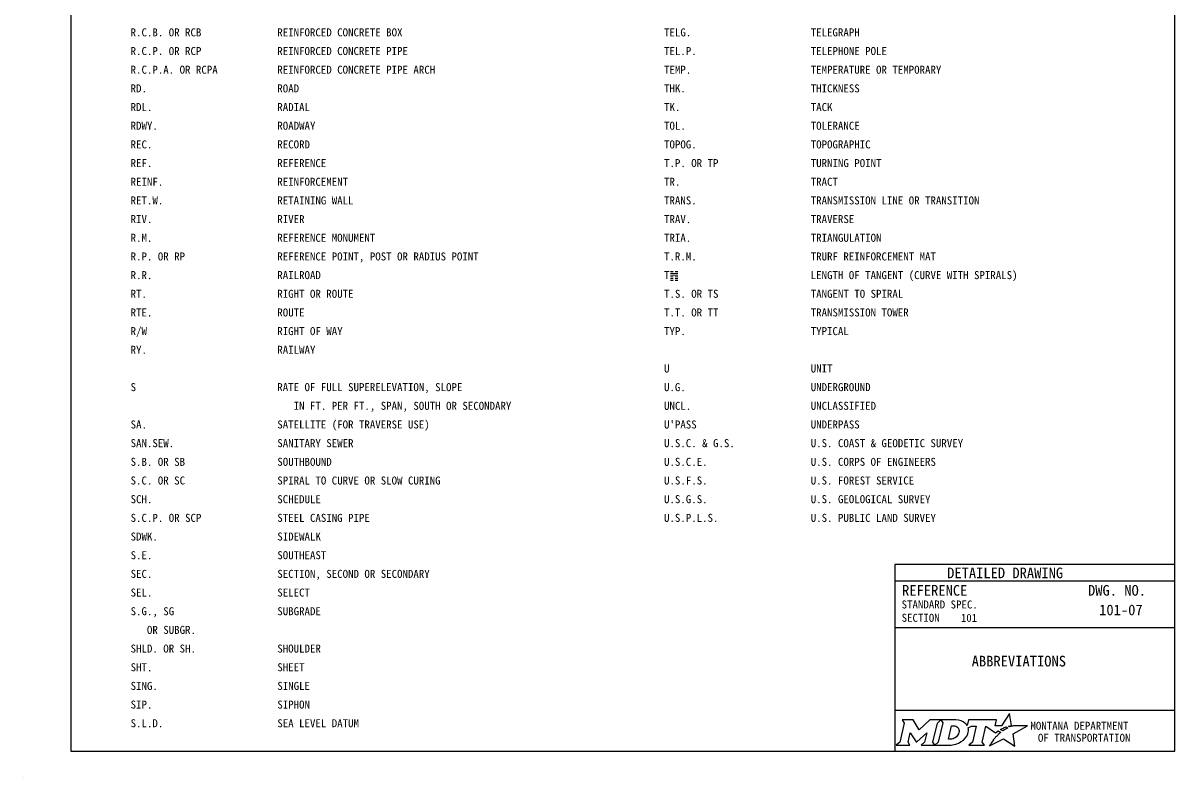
# Model space of a CAD drawing. Extents: x 49991.4 to 50021, y 49987.6 to 50011.4.
# Drawn here: x 49999.98 to 50008.61, y 49999.86 to 50005.52 of the extents above; entities that cross this region are included whole.
import ezdxf

# ---------------------------------------------------------------- set-up
doc = ezdxf.new("R2010")
doc.units = 0
for name, color, linetype in [('Level 1', 7, 'Continuous'), ('Level 2', 7, 'Continuous'), ('Level 5', 7, 'Continuous')]:
    doc.layers.add(name, color=color, linetype=linetype)

msp = doc.modelspace()

# ---------------------------------------------------------------- linework, layer by layer
at = {"layer": 'Level 1'}
msp.add_line((49999.9766, 49999.8624), (49999.9766, 49999.8624), dxfattribs=at)
msp.add_lwpolyline([(50008.6146, 50011.2628), (50000.3356, 50011.2628), (50000.3356, 50000.0624), (50008.6146, 50000.0624)], close=True, dxfattribs=at)
at = {"layer": 'Level 2'}
for p, q in [((50008.6146, 50001.4624), (50006.5146, 50001.4624)), ((50006.5146, 50001.4624), (50006.5146, 50000.0624)), ((50008.6146, 50001.3374), (50006.5146, 50001.3374)), ((50008.2507, 50001.1223), (50008.2507, 50001.1223)), ((50008.6146, 50000.9874), (50006.5146, 50000.9874)), ((50007.0089, 50001.0629), (50007.0089, 50001.0629)), ((50007.5646, 50000.7383), (50007.5646, 50000.7383)), ((50008.6146, 50000.3693), (50006.5146, 50000.3693))]:
    msp.add_line(p, q, dxfattribs=at)
for points in [[(50006.5701, 50000.2974), (50006.5842, 50000.274), (50006.5507, 50000.1307), (50006.525, 50000.1082), (50006.6266, 50000.1082), (50006.6131, 50000.131), (50006.6293, 50000.2011), (50006.673, 50000.1321), (50006.6783, 50000.1321), (50006.7534, 50000.2016), (50006.737, 50000.1305), (50006.7123, 50000.1085), (50006.8139, 50000.1085), (50006.8001, 50000.1318), (50006.8333, 50000.2742)], [(50006.8333, 50000.2742), (50006.8586, 50000.2974), (50006.7762, 50000.2974), (50006.6966, 50000.2244), (50006.6521, 50000.2971), (50006.5701, 50000.2974)], [(50006.9722, 50000.2974), (50006.8586, 50000.2974), (50006.8733, 50000.2745), (50006.8394, 50000.1307), (50006.8139, 50000.1085), (50006.9245, 50000.1085)], [(50007.3771, 50000.2447), (50007.3668, 50000.2503), (50007.3784, 50000.2531), (50007.39, 50000.2551), (50007.3726, 50000.3452), (50007.3131, 50000.2539), (50007.2658, 50000.2532), (50007.2761, 50000.2973), (50007.0669, 50000.2974), (50007.0568, 50000.2549), (50007.051, 50000.2632)], [(50006.9962, 50000.2107), (50006.995, 50000.2026), (50006.9918, 50000.1933), (50006.9876, 50000.1851), (50006.982, 50000.1776), (50006.9755, 50000.1707), (50006.9676, 50000.1644), (50006.9593, 50000.1597), (50006.9502, 50000.1558), (50006.9411, 50000.1535), (50006.9319, 50000.1526), (50006.916, 50000.1526), (50006.9396, 50000.2526), (50006.9556, 50000.2526), (50006.9632, 50000.252), (50006.9708, 50000.2501), (50006.9774, 50000.2471), (50006.9835, 50000.2429), (50006.9883, 50000.2379), (50006.992, 50000.2319), (50006.9947, 50000.2257), (50006.9963, 50000.2183), (50006.9963, 50000.2153), (50006.9962, 50000.2107)], [(50007.0636, 50000.2383), (50007.0882, 50000.2514), (50007.1251, 50000.2514), (50007.0965, 50000.1309), (50007.069, 50000.1082), (50007.1852, 50000.1082), (50007.1682, 50000.1311), (50007.1964, 50000.2513), (50007.2677, 50000.1996), (50007.2888, 50000.2147), (50007.3085, 50000.2038)], [(50007.2527, 50000.1479), (50007.2374, 50000.1235), (50007.2327, 50000.116), (50007.2269, 50000.1074), (50007.2246, 50000.1031), (50007.3299, 50000.1562), (50007.4138, 50000.1011), (50007.4007, 50000.1938), (50007.5076, 50000.2522), (50007.4583, 50000.253), (50007.4282, 50000.2534), (50007.4074, 50000.2537), (50007.4006, 50000.2522), (50007.3957, 50000.251), (50007.3873, 50000.2487), (50007.3771, 50000.2447)], [(50007.3267, 50000.2171), (50007.3243, 50000.2154), (50007.306, 50000.225), (50007.3163, 50000.2307), (50007.3204, 50000.2329), (50007.329, 50000.2369), (50007.3347, 50000.2395), (50007.3426, 50000.2425), (50007.3499, 50000.2452), (50007.3617, 50000.2378), (50007.3577, 50000.2357), (50007.3531, 50000.2332), (50007.3489, 50000.231), (50007.3439, 50000.2281), (50007.342, 50000.227), (50007.3393, 50000.2254), (50007.3368, 50000.224), (50007.3345, 50000.2224), (50007.3319, 50000.2206), (50007.3292, 50000.2188), (50007.3267, 50000.2171)], [(50006.9702, 50000.1158), (50006.9786, 50000.1184), (50006.9916, 50000.1238), (50007.012, 50000.1348)], [(50007.2666, 50000.164), (50007.2666, 50000.164)]]:
    msp.add_lwpolyline(points, dxfattribs=at)
for centre, radius, start, end in [((50006.9953, 50000.219), 0.0709, 339.53292, 15.85821), ((50006.9513, 50000.2363), 0.1183, 300.91025, 339.13831)]:
    msp.add_arc(centre, radius, start, end, dxfattribs=at)
for centre, major_axis, ratio, start_param, end_param in [((50006.9701, 50000.25), (0.0834, -0.0037), 0.568097, 0.61298, 1.570796), ((50007.0257, 50000.2573), (0.0361, -0.0295), 0.469099, 1.225588, 1.570796), ((50007.2974, 50000.1941), (-0.0112, -0.0097), 0.021651, 3.157348, 6.283185), ((50006.9248, 50000.2568), (0, 0.1484), 0.987302, 3.139398, 3.456847), ((50007.2597, 50000.1559), (-0.00694, -0.00806), 0.008222, 0, 3.137361), ((50007.2764, 50000.1742), (-0.0098, -0.0102), 0.016458, 3.141593, 6.279097)]:
    msp.add_ellipse(centre, major_axis=major_axis, ratio=ratio, start_param=start_param, end_param=end_param, dxfattribs=at)

# ---------------------------------------------------------------- texts
for s, height, p in [('R.C.B. OR RCB  ', 0.06, (50000.7833, 50005.4226)), ('REINFORCED CONCRETE BOX                 ', 0.06, (50001.8833, 50005.4226)), ('TELG.          ', 0.06, (50004.7833, 50005.4226)), ('TELEGRAPH                               ', 0.06, (50005.8833, 50005.4226)), ('R.C.P. OR RCP  ', 0.06, (50000.7833, 50005.2826)), ('REINFORCED CONCRETE PIPE                ', 0.06, (50001.8833, 50005.2826)), ('TEL.P.         ', 0.06, (50004.7833, 50005.2826)), ('TELEPHONE POLE                          ', 0.06, (50005.8833, 50005.2826)), ('R.C.P.A. OR RCPA', 0.06, (50000.7833, 50005.1426)), ('REINFORCED CONCRETE PIPE ARCH           ', 0.06, (50001.8833, 50005.1426)), ('TEMP.          ', 0.06, (50004.7833, 50005.1426)), ('TEMPERATURE OR TEMPORARY                ', 0.06, (50005.8833, 50005.1426)), ('RD.            ', 0.06, (50000.7833, 50005.0026)), ('ROAD                                    ', 0.06, (50001.8833, 50005.0026)), ('THK.           ', 0.06, (50004.7833, 50005.0026)), ('THICKNESS                               ', 0.06, (50005.8833, 50005.0026)), ('RDL.           ', 0.06, (50000.7833, 50004.8626)), ('RADIAL                                  ', 0.06, (50001.8833, 50004.8626)), ('TK.            ', 0.06, (50004.7833, 50004.8626)), ('TACK                                    ', 0.06, (50005.8833, 50004.8626)), ('RDWY.          ', 0.06, (50000.7833, 50004.7226)), ('ROADWAY                                 ', 0.06, (50001.8833, 50004.7226)), ('TOL.            ', 0.06, (50004.7833, 50004.7226)), ('TOLERANCE                                   ', 0.06, (50005.8833, 50004.7226)), ('REC.           ', 0.06, (50000.7833, 50004.5826)), ('RECORD                                  ', 0.06, (50001.8833, 50004.5826)), ('TOPOG.         ', 0.06, (50004.7833, 50004.5826)), ('TOPOGRAPHIC                             ', 0.06, (50005.8833, 50004.5826)), ('REF.           ', 0.06, (50000.7833, 50004.4426)), ('REFERENCE                               ', 0.06, (50001.8833, 50004.4426)), ('T.P. OR TP     ', 0.06, (50004.7833, 50004.4426)), ('TURNING POINT                           ', 0.06, (50005.8833, 50004.4426)), ('REINF.         ', 0.06, (50000.7833, 50004.3026)), ('REINFORCEMENT                           ', 0.06, (50001.8833, 50004.3026)), ('TR.            ', 0.06, (50004.7833, 50004.3026)), ('TRACT                                   ', 0.06, (50005.8833, 50004.3026)), ('RET.W.         ', 0.06, (50000.7833, 50004.1626)), ('RETAINING WALL                          ', 0.06, (50001.8833, 50004.1626)), ('TRANS.         ', 0.06, (50004.7833, 50004.1626)), ('TRANSMISSION LINE OR TRANSITION         ', 0.06, (50005.8833, 50004.1626)), ('RIV.           ', 0.06, (50000.7833, 50004.0226)), ('RIVER                                   ', 0.06, (50001.8833, 50004.0226)), ('TRAV.          ', 0.06, (50004.7833, 50004.0226)), ('TRAVERSE                                ', 0.06, (50005.8833, 50004.0226)), ('R.M.           ', 0.06, (50000.7833, 50003.8826)), ('REFERENCE MONUMENT                      ', 0.06, (50001.8833, 50003.8826)), ('TRIA.          ', 0.06, (50004.7833, 50003.8826)), ('TRIANGULATION                           ', 0.06, (50005.8833, 50003.8826)), ('R.P. OR RP     ', 0.06, (50000.7833, 50003.7426)), ('REFERENCE POINT, POST OR RADIUS POINT   ', 0.06, (50001.8833, 50003.7426)), ('T.R.M.          ', 0.06, (50004.7833, 50003.7426)), ('TRURF REINFORCEMENT MAT                           ', 0.06, (50005.8833, 50003.7426)), ('R.R.           ', 0.06, (50000.7833, 50003.6026)), ('RAILROAD                                ', 0.06, (50001.8833, 50003.6026)), ('T䷬', 0.06, (50004.7833, 50003.6026)), ('LENGTH OF TANGENT (CURVE WITH SPIRALS)  ', 0.06, (50005.8833, 50003.6026)), ('RT.            ', 0.06, (50000.7833, 50003.4626)), ('RIGHT OR ROUTE                          ', 0.06, (50001.8833, 50003.4626)), ('T.S. OR TS     ', 0.06, (50004.7833, 50003.4626)), ('TANGENT TO SPIRAL                       ', 0.06, (50005.8833, 50003.4626)), ('RTE.           ', 0.06, (50000.7833, 50003.3226)), ('ROUTE                                   ', 0.06, (50001.8833, 50003.3226)), ('T.T. OR TT     ', 0.06, (50004.7833, 50003.3226)), ('TRANSMISSION TOWER                      ', 0.06, (50005.8833, 50003.3226)), ('R/W            ', 0.06, (50000.7833, 50003.1826)), ('RIGHT OF WAY                            ', 0.06, (50001.8833, 50003.1826)), ('TYP.           ', 0.06, (50004.7833, 50003.1826)), ('TYPICAL                                 ', 0.06, (50005.8833, 50003.1826)), ('RY.            ', 0.06, (50000.7833, 50003.0426)), ('RAILWAY                                 ', 0.06, (50001.8833, 50003.0426)), ('U              ', 0.06, (50004.7833, 50002.9026)), ('UNIT                                    ', 0.06, (50005.8833, 50002.9026)), ('S              ', 0.06, (50000.7833, 50002.7626)), ('RATE OF FULL SUPERELEVATION, SLOPE      ', 0.06, (50001.8833, 50002.7626)), ('U.G.           ', 0.06, (50004.7833, 50002.7626)), ('UNDERGROUND                             ', 0.06, (50005.8833, 50002.7626)), ('   IN FT. PER FT., SPAN, SOUTH OR SECONDARY', 0.06, (50001.8833, 50002.6226)), ('UNCL.          ', 0.06, (50004.7833, 50002.6226)), ('UNCLASSIFIED                            ', 0.06, (50005.8833, 50002.6226)), ('SA.            ', 0.06, (50000.7833, 50002.4826)), ('SATELLITE (FOR TRAVERSE USE)            ', 0.06, (50001.8833, 50002.4826)), ("U'PASS         ", 0.06, (50004.7833, 50002.4826)), ('UNDERPASS                               ', 0.06, (50005.8833, 50002.4826)), ('SAN.SEW.       ', 0.06, (50000.7833, 50002.3426)), ('SANITARY SEWER                          ', 0.06, (50001.8833, 50002.3426)), ('U.S.C. & G.S.  ', 0.06, (50004.7833, 50002.3426)), ('U.S. COAST & GEODETIC SURVEY            ', 0.06, (50005.8833, 50002.3426)), ('S.B. OR SB     ', 0.06, (50000.7833, 50002.2026)), ('SOUTHBOUND                              ', 0.06, (50001.8833, 50002.2026)), ('U.S.C.E.       ', 0.06, (50004.7833, 50002.2026)), ('U.S. CORPS OF ENGINEERS                 ', 0.06, (50005.8833, 50002.2026)), ('S.C. OR SC     ', 0.06, (50000.7833, 50002.0626)), ('SPIRAL TO CURVE OR SLOW CURING          ', 0.06, (50001.8833, 50002.0626)), ('U.S.F.S.       ', 0.06, (50004.7833, 50002.0626)), ('U.S. FOREST SERVICE                     ', 0.06, (50005.8833, 50002.0626)), ('SCH.           ', 0.06, (50000.7833, 50001.9226)), ('SCHEDULE                                ', 0.06, (50001.8833, 50001.9226)), ('U.S.G.S.       ', 0.06, (50004.7833, 50001.9226)), ('U.S. GEOLOGICAL SURVEY                  ', 0.06, (50005.8833, 50001.9226)), ('S.C.P. OR SCP', 0.06, (50000.7833, 50001.7826)), ('STEEL CASING PIPE', 0.06, (50001.8833, 50001.7826)), ('U.S.P.L.S.     ', 0.06, (50004.7833, 50001.7826)), ('U.S. PUBLIC LAND SURVEY                 ', 0.06, (50005.8833, 50001.7826)), ('SDWK.          ', 0.06, (50000.7833, 50001.6426)), ('SIDEWALK                                ', 0.06, (50001.8833, 50001.6426)), ('S.E.           ', 0.06, (50000.7833, 50001.5026)), ('SOUTHEAST                               ', 0.06, (50001.8833, 50001.5026)), ('SEC.           ', 0.06, (50000.7833, 50001.3626)), ('SECTION, SECOND OR SECONDARY            ', 0.06, (50001.8833, 50001.3626)), ('SEL.           ', 0.06, (50000.7833, 50001.2226)), ('SELECT                                  ', 0.06, (50001.8833, 50001.2226)), ('REFERENCE', 0.08, (50006.5682, 50001.229)), ('DWG. NO.', 0.08, (50007.9624, 50001.229)), ('STANDARD SPEC.', 0.06, (50006.5649, 50001.133)), ('101-07', 0.08, (50008.0459, 50001.0823)), ('S.G., SG', 0.06, (50000.7833, 50001.0826)), ('SUBGRADE                                ', 0.06, (50001.8833, 50001.0826)), ('SECTION', 0.06, (50006.5649, 50001.033)), ('101', 0.06, (50007.0089, 50001.0329)), ('   OR SUBGR.      ', 0.06, (50000.7833, 50000.9426)), ('SHLD. OR SH.   ', 0.06, (50000.7833, 50000.8026)), ('SHOULDER                                ', 0.06, (50001.8833, 50000.8026)), ('SHT.           ', 0.06, (50000.7833, 50000.6626)), ('SHEET                                   ', 0.06, (50001.8833, 50000.6626)), ('ABBREVIATIONS', 0.08, (50007.09, 50000.6983)), ('SING.          ', 0.06, (50000.7833, 50000.5226)), ('SINGLE                                  ', 0.06, (50001.8833, 50000.5226)), ('SIP.           ', 0.06, (50000.7833, 50000.3826)), ('SIPHON                                  ', 0.06, (50001.8833, 50000.3826)), ('S.L.D.         ', 0.06, (50000.7833, 50000.2426)), ('SEA LEVEL DATUM                         ', 0.06, (50001.8833, 50000.2426)), ('MONTANA DEPARTMENT', 0.06, (50007.5308, 50000.2236)), ('OF TRANSPORTATION', 0.06, (50007.587, 50000.1336))]:
    msp.add_text(s, height=height, dxfattribs=at).set_placement(p)
at = {"layer": 'Level 5'}
msp.add_text('DETAILED DRAWING', height=0.0799, dxfattribs=at).set_placement((50006.9063, 50001.3599))

doc.saveas('drawing.dxf')
